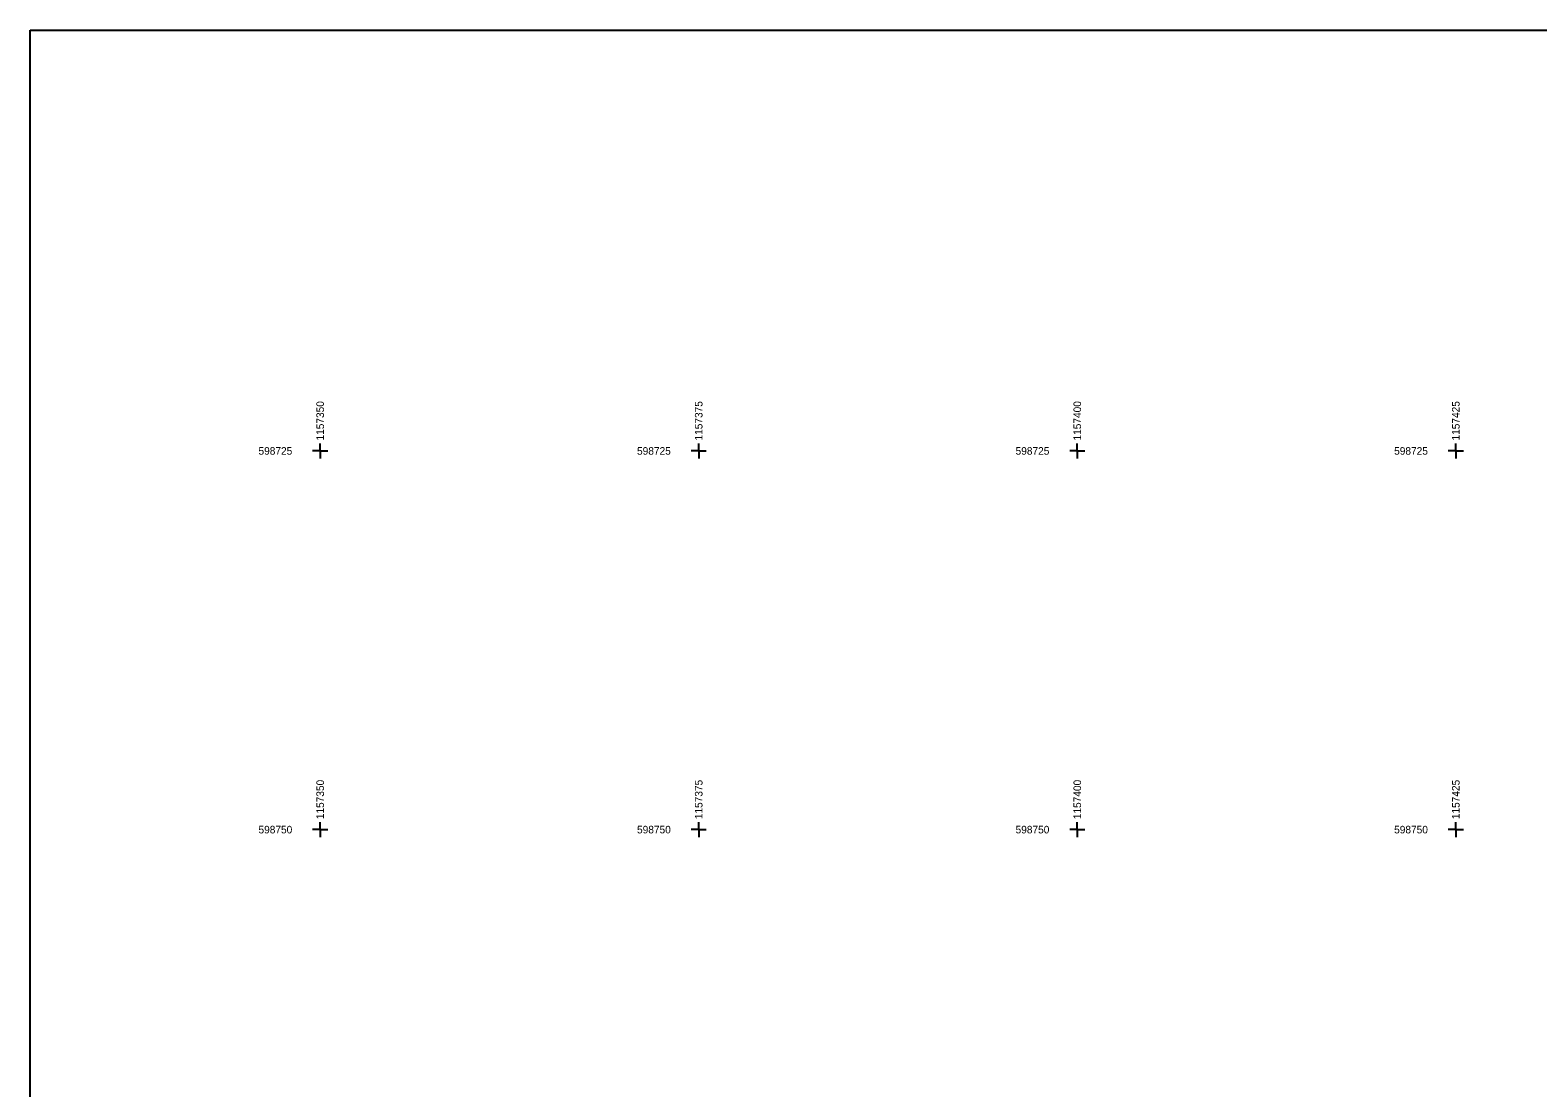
# Model space of a CAD drawing. Extents: x -598874 to -598664, y -1157512 to -1157364.
# Drawn here: x -598874.5 to -598774.9, y -1157434.2 to -1157364.4 of the extents above; entities that cross this region are included whole.
import ezdxf

# ---------------------------------------------------------------- set-up
doc = ezdxf.new("R2010")
doc.units = 0
for name, color, linetype in [('Vrstva 1', 7, 'Continuous'), ('Vrstva 52', 7, 'Continuous'), ('Vrstva 62', 7, 'Continuous')]:
    doc.layers.add(name, color=color, linetype=linetype)

msp = doc.modelspace()

# ---------------------------------------------------------------- linework, layer by layer
at = {"layer": 'Vrstva 1'}
for p, q in [((-598874.499, -1157512.412), (-598874.499, -1157364.413)), ((-598874.499, -1157364.413), (-598664.499, -1157364.413))]:
    msp.add_line(p, q, dxfattribs=at)
at = {"layer": 'Vrstva 62'}
for p, q in [((-598855.346, -1157392.191), (-598855.846, -1157392.191)), ((-598855.346, -1157392.191), (-598855.346, -1157391.691)), ((-598855.346, -1157392.191), (-598855.346, -1157392.691)), ((-598855.346, -1157392.191), (-598854.846, -1157392.191)), ((-598830.346, -1157392.191), (-598830.846, -1157392.191)), ((-598830.346, -1157392.191), (-598830.346, -1157391.691)), ((-598830.346, -1157392.191), (-598830.346, -1157392.691)), ((-598830.346, -1157392.191), (-598829.846, -1157392.191)), ((-598805.346, -1157392.191), (-598805.846, -1157392.191)), ((-598805.346, -1157392.191), (-598805.346, -1157391.691)), ((-598805.346, -1157392.191), (-598805.346, -1157392.691)), ((-598805.346, -1157392.191), (-598804.846, -1157392.191)), ((-598780.346, -1157392.191), (-598780.846, -1157392.191)), ((-598780.346, -1157392.191), (-598780.346, -1157391.691)), ((-598780.346, -1157392.191), (-598780.346, -1157392.691)), ((-598780.346, -1157392.191), (-598779.846, -1157392.191)), ((-598855.346, -1157417.191), (-598855.846, -1157417.191)), ((-598855.346, -1157417.191), (-598855.346, -1157416.691)), ((-598855.346, -1157417.191), (-598855.346, -1157417.691)), ((-598855.346, -1157417.191), (-598854.846, -1157417.191)), ((-598830.346, -1157417.191), (-598830.846, -1157417.191)), ((-598830.346, -1157417.191), (-598830.346, -1157416.691)), ((-598830.346, -1157417.191), (-598830.346, -1157417.691)), ((-598830.346, -1157417.191), (-598829.846, -1157417.191)), ((-598805.346, -1157417.191), (-598805.846, -1157417.191)), ((-598805.346, -1157417.191), (-598805.346, -1157416.691)), ((-598805.346, -1157417.191), (-598805.346, -1157417.691)), ((-598805.346, -1157417.191), (-598804.846, -1157417.191)), ((-598780.346, -1157417.191), (-598780.846, -1157417.191)), ((-598780.346, -1157417.191), (-598780.346, -1157416.691)), ((-598780.346, -1157417.191), (-598780.346, -1157417.691)), ((-598780.346, -1157417.191), (-598779.846, -1157417.191))]:
    msp.add_line(p, q, dxfattribs=at)

# ---------------------------------------------------------------- texts
at = {"layer": 'Vrstva 52'}
for s, rotation, p in [(' 1157350', 90, (-598855.096, -1157391.691)), (' 1157375', 90, (-598830.096, -1157391.691)), (' 1157400', 90, (-598805.096, -1157391.691)), (' 1157425', 90, (-598780.096, -1157391.691)), (' 598725', 360, (-598859.605, -1157392.441)), (' 598725', 360, (-598834.605, -1157392.441)), (' 598725', 360, (-598809.605, -1157392.441)), (' 598725', 360, (-598784.605, -1157392.441)), (' 1157350', 90, (-598855.096, -1157416.691)), (' 1157375', 90, (-598830.096, -1157416.691)), (' 1157400', 90, (-598805.096, -1157416.691)), (' 1157425', 90, (-598780.096, -1157416.691)), (' 598750', 360, (-598859.605, -1157417.441)), (' 598750', 360, (-598834.605, -1157417.441)), (' 598750', 360, (-598809.605, -1157417.441)), (' 598750', 360, (-598784.605, -1157417.441))]:
    msp.add_text(s, height=0.5, rotation=rotation, dxfattribs=at).set_placement(p)

doc.saveas('drawing.dxf')
